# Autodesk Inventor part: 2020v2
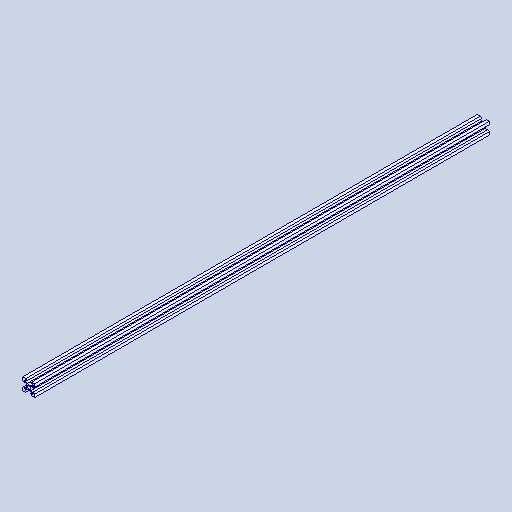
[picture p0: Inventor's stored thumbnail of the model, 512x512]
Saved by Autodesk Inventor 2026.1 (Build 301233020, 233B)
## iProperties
Created: 2024-09
Part Number: 2020v2
Material: Alluminio 6061
Document SubType Name: Modeling
Designer: hp
Density: 2.7 g/cm^3
Appearance: Default
Author: hp
Revision Number: ANY
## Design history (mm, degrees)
node "Solido1"
sketch "Sketch3"
  geometry: 2 further points
hole "Hole3" sketch "Sketch3" at (32.222, -3.027), (16.972, -3.027) diameter "d14" = 4.5; stored, may be unused: countersink angle "d18" = 90 deg, drill point angle "d20" = 0 deg; dims "d15" = 6, "d16" = 4, "d17" = 2, "d19" = 8
sketch "Sketch8"
  geometry: 2 further points
hole "Hole8" sketch "Sketch8" at (742, 3.053), (755, 3.053) diameter "d49" = 4.5; stored, may be unused: countersink angle "d53" = 90 deg, drill point angle "d55" = 0 deg; dims "d50" = 6, "d51" = 4, "d52" = 2, "d54" = 8
sketch "Sketch9"
  geometry: 2 further points
hole "Hole9" sketch "Sketch9" at (690.765, -3.027), (714.765, -3.027) diameter "d56" = 3.4; stored, may be unused: countersink angle "d60" = 90 deg, drill point angle "d62" = 0 deg; dims "d57" = 6, "d58" = 4, "d59" = 2, "d61" = 8
sketch "Sketch10"
  geometry: 1 further point
hole "Hole10" sketch "Sketch10" at (82.6, -3.277) diameter "d63" = 4.5; stored, may be unused: countersink angle "d67" = 90 deg, drill point angle "d69" = 0 deg; dims "d64" = 6, "d65" = 4, "d66" = 2, "d68" = 8
sketch "Sketch11"
  geometry: 1 further point
hole "Hole11" sketch "Sketch11" at (42.9, -3.277) diameter "d70" = 4.5; stored, may be unused: countersink angle "d74" = 90 deg, drill point angle "d76" = 0 deg; dims "d71" = 6, "d72" = 4, "d73" = 2, "d75" = 8
body "Solid1"
